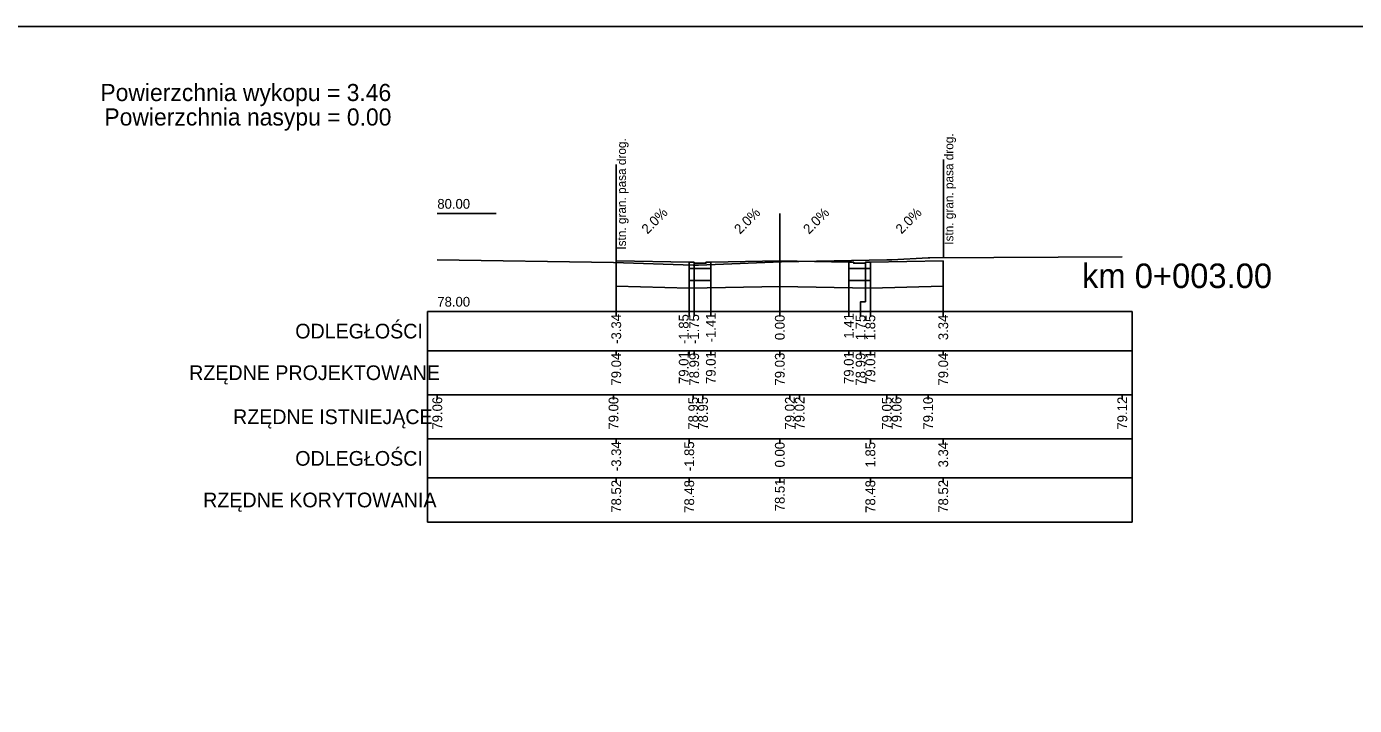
# Model space of a CAD drawing. Extents: x 7492871 to 7493499, y 5802964 to 5802992.
# Drawn here: x 7493105.36 to 7493132.5, y 5802978.41 to 5802992.28 of the extents above; entities that cross this region are included whole.
import ezdxf

# ---------------------------------------------------------------- set-up
doc = ezdxf.new("R2010")
doc.units = 0
for name, color, linetype in [('_wydruk', 7, 'Continuous'), ('d_pop_nasyp_opis', 7, 'Continuous'), ('d_pop_wykop_opis', 7, 'Continuous'), ('opisy_ramki_pop', 7, 'Continuous'), ('pop_comp_kostka', 7, 'Continuous'), ('pop_comp_lawa', 7, 'Continuous'), ('pop_comp_scieralna', 7, 'Continuous'), ('pop_granica_istn', 7, 'Continuous'), ('pop_opis', 7, 'Continuous'), ('pop_os', 7, 'Continuous'), ('pop_pikietaz', 7, 'Continuous'), ('pop_teren', 7, 'Continuous')]:
    doc.layers.add(name, color=color, linetype=linetype)

msp = doc.modelspace()

# ---------------------------------------------------------------- linework, layer by layer
msp.add_lwpolyline([(7493117.413, 5802987.495), (7493118.905, 5802987.465), (7493119.005, 5802987.465), (7493119.006, 5802987.445), (7493119.245, 5802987.445), (7493119.246, 5802987.465), (7493119.346, 5802987.465), (7493120.756, 5802987.493), (7493122.166, 5802987.465), (7493122.266, 5802987.465), (7493122.267, 5802987.445), (7493122.506, 5802987.445), (7493122.507, 5802987.465), (7493122.607, 5802987.465), (7493124.097, 5802987.495)])
at = {"layer": '_wydruk'}
msp.add_lwpolyline([(7492871.369, 5802992.281), (7493499.283, 5802992.281), (7493499.283, 5802963.881), (7492871.369, 5802963.881)], close=True, dxfattribs=at)
at = {"layer": 'opisy_ramki_pop'}
for points in [[(7493117.413, 5802986.975), (7493117.413, 5802986.659), (7493117.413, 5802986.659), (7493117.413, 5802986.459)], [(7493118.905, 5802986.936), (7493118.905, 5802986.659), (7493118.905, 5802986.659), (7493118.905, 5802986.459)], [(7493120.756, 5802986.973), (7493120.756, 5802986.659), (7493120.756, 5802986.659), (7493120.756, 5802986.459)], [(7493122.607, 5802986.936), (7493122.607, 5802986.659), (7493122.607, 5802986.659), (7493122.607, 5802986.459)], [(7493124.097, 5802986.975), (7493124.097, 5802986.659), (7493124.097, 5802986.659), (7493124.097, 5802986.459)]]:
    msp.add_lwpolyline(points, dxfattribs=at)
at = {"layer": 'pop_comp_kostka'}
for p, q in [((7493119.005, 5802987.465), (7493118.905, 5802987.465)), ((7493118.905, 5802987.465), (7493118.905, 5802987.335)), ((7493119.006, 5802987.445), (7493119.005, 5802987.465)), ((7493119.245, 5802987.445), (7493119.006, 5802987.445)), ((7493119.246, 5802987.465), (7493119.245, 5802987.445)), ((7493119.346, 5802987.465), (7493119.246, 5802987.465)), ((7493119.346, 5802987.335), (7493119.346, 5802987.465)), ((7493122.266, 5802987.465), (7493122.166, 5802987.465)), ((7493122.166, 5802987.465), (7493122.166, 5802987.335)), ((7493122.267, 5802987.445), (7493122.266, 5802987.465)), ((7493122.506, 5802987.445), (7493122.267, 5802987.445)), ((7493122.507, 5802987.465), (7493122.506, 5802987.445)), ((7493122.607, 5802987.465), (7493122.507, 5802987.465)), ((7493122.607, 5802987.335), (7493122.607, 5802987.465)), ((7493118.905, 5802987.335), (7493119.346, 5802987.335)), ((7493122.166, 5802987.335), (7493122.607, 5802987.335))]:
    msp.add_line(p, q, dxfattribs=at)
at = {"layer": 'pop_comp_lawa'}
for p, q in [((7493119.346, 5802987.335), (7493118.905, 5802987.335)), ((7493118.905, 5802987.335), (7493118.905, 5802987.095)), ((7493119.346, 5802987.095), (7493119.346, 5802987.335)), ((7493122.607, 5802987.335), (7493122.166, 5802987.335)), ((7493122.166, 5802987.335), (7493122.166, 5802987.095)), ((7493122.607, 5802987.095), (7493122.607, 5802987.335)), ((7493118.905, 5802987.095), (7493119.346, 5802987.095)), ((7493122.166, 5802987.095), (7493122.607, 5802987.095))]:
    msp.add_line(p, q, dxfattribs=at)
at = {"layer": 'pop_comp_scieralna'}
for p, q in [((7493118.905, 5802987.465), (7493117.413, 5802987.495)), ((7493117.413, 5802987.495), (7493117.413, 5802986.975)), ((7493118.905, 5802987.095), (7493118.905, 5802987.465)), ((7493120.756, 5802987.493), (7493119.346, 5802987.465)), ((7493119.346, 5802987.465), (7493119.346, 5802987.095)), ((7493120.756, 5802986.973), (7493120.756, 5802987.493)), ((7493122.166, 5802987.465), (7493120.756, 5802987.493)), ((7493120.756, 5802987.493), (7493120.756, 5802986.973)), ((7493122.166, 5802987.095), (7493122.166, 5802987.465)), ((7493124.097, 5802987.495), (7493122.607, 5802987.465)), ((7493122.607, 5802987.465), (7493122.607, 5802987.095)), ((7493124.097, 5802986.975), (7493124.097, 5802987.495)), ((7493117.413, 5802986.975), (7493118.905, 5802986.936)), ((7493119.346, 5802987.095), (7493118.905, 5802987.095)), ((7493118.905, 5802986.936), (7493120.756, 5802986.973)), ((7493120.756, 5802986.973), (7493122.607, 5802986.936)), ((7493122.607, 5802987.095), (7493122.166, 5802987.095)), ((7493122.607, 5802986.936), (7493124.097, 5802986.975))]:
    msp.add_line(p, q, dxfattribs=at)
at = {"layer": 'pop_granica_istn'}
for p, q in [((7493117.413, 5802987.963), (7493117.413, 5802989.463)), ((7493124.105, 5802988.062), (7493124.105, 5802989.562)), ((7493124.105, 5802987.562), (7493124.105, 5802988.062)), ((7493117.413, 5802987.463), (7493117.413, 5802987.963))]:
    msp.add_line(p, q, dxfattribs=at)
at = {"layer": 'pop_opis'}
for p, q in [((7493113.756, 5802988.459), (7493114.956, 5802988.459)), ((7493113.556, 5802986.459), (7493113.556, 5802984.759)), ((7493113.556, 5802986.459), (7493113.556, 5802984.759)), ((7493113.556, 5802986.459), (7493113.556, 5802984.759)), ((7493113.556, 5802986.459), (7493113.556, 5802984.759)), ((7493113.756, 5802986.459), (7493114.956, 5802986.459)), ((7493117.413, 5802986.359), (7493117.413, 5802986.459)), ((7493118.905, 5802986.359), (7493118.905, 5802986.459)), ((7493119.006, 5802986.359), (7493119.006, 5802986.459)), ((7493119.346, 5802986.359), (7493119.346, 5802986.459)), ((7493120.756, 5802986.359), (7493120.756, 5802986.459)), ((7493122.166, 5802986.359), (7493122.166, 5802986.459)), ((7493122.407, 5802986.359), (7493122.407, 5802986.459)), ((7493122.607, 5802986.359), (7493122.607, 5802986.459)), ((7493124.097, 5802986.359), (7493124.097, 5802986.459)), ((7493113.556, 5802985.659), (7493127.956, 5802985.659)), ((7493113.556, 5802985.659), (7493127.956, 5802985.659)), ((7493113.556, 5802985.659), (7493127.956, 5802985.659)), ((7493113.556, 5802985.659), (7493127.956, 5802985.659)), ((7493117.413, 5802985.559), (7493117.413, 5802985.659)), ((7493118.905, 5802985.559), (7493118.905, 5802985.659)), ((7493119.006, 5802985.559), (7493119.006, 5802985.659)), ((7493119.346, 5802985.559), (7493119.346, 5802985.659)), ((7493120.756, 5802985.559), (7493120.756, 5802985.659)), ((7493122.166, 5802985.559), (7493122.166, 5802985.659)), ((7493122.407, 5802985.559), (7493122.407, 5802985.659)), ((7493122.607, 5802985.559), (7493122.607, 5802985.659)), ((7493124.097, 5802985.559), (7493124.097, 5802985.659)), ((7493113.556, 5802984.759), (7493113.556, 5802983.859)), ((7493113.756, 5802984.659), (7493113.756, 5802984.759)), ((7493117.357, 5802984.659), (7493117.357, 5802984.759)), ((7493118.986, 5802984.659), (7493118.986, 5802984.759)), ((7493119.186, 5802984.659), (7493119.186, 5802984.759)), ((7493120.961, 5802984.659), (7493120.961, 5802984.759)), ((7493121.161, 5802984.659), (7493121.161, 5802984.759)), ((7493122.944, 5802984.659), (7493122.944, 5802984.759)), ((7493123.144, 5802984.659), (7493123.144, 5802984.759)), ((7493123.787, 5802984.659), (7493123.787, 5802984.759)), ((7493127.756, 5802984.659), (7493127.756, 5802984.759)), ((7493113.556, 5802983.859), (7493113.556, 5802982.159)), ((7493117.413, 5802983.759), (7493117.413, 5802983.859)), ((7493118.905, 5802983.759), (7493118.905, 5802983.859)), ((7493120.756, 5802983.759), (7493120.756, 5802983.859)), ((7493122.607, 5802983.759), (7493122.607, 5802983.859)), ((7493124.097, 5802983.759), (7493124.097, 5802983.859)), ((7493113.556, 5802983.059), (7493127.956, 5802983.059)), ((7493117.413, 5802982.959), (7493117.413, 5802983.059)), ((7493118.905, 5802982.959), (7493118.905, 5802983.059)), ((7493120.756, 5802982.959), (7493120.756, 5802983.059)), ((7493122.607, 5802982.959), (7493122.607, 5802983.059)), ((7493124.097, 5802982.959), (7493124.097, 5802983.059))]:
    msp.add_line(p, q, dxfattribs=at)
for points in [[(7493117.413, 5802987.495), (7493117.413, 5802986.659), (7493117.413, 5802986.659), (7493117.413, 5802986.459)], [(7493118.905, 5802987.465), (7493118.905, 5802986.659), (7493118.905, 5802986.659), (7493118.905, 5802986.459)], [(7493119.006, 5802987.445), (7493119.006, 5802986.659), (7493119.006, 5802986.659), (7493119.006, 5802986.459)], [(7493119.346, 5802987.465), (7493119.346, 5802986.659), (7493119.346, 5802986.659), (7493119.346, 5802986.459)], [(7493120.756, 5802987.493), (7493120.756, 5802986.659), (7493120.756, 5802986.659), (7493120.756, 5802986.459)], [(7493122.166, 5802987.465), (7493122.166, 5802986.659), (7493122.166, 5802986.659), (7493122.166, 5802986.459)], [(7493122.506, 5802987.445), (7493122.506, 5802986.659), (7493122.407, 5802986.659), (7493122.407, 5802986.459)], [(7493122.607, 5802987.465), (7493122.607, 5802986.659), (7493122.607, 5802986.659), (7493122.607, 5802986.459)], [(7493124.097, 5802987.495), (7493124.097, 5802986.659), (7493124.097, 5802986.659), (7493124.097, 5802986.459)]]:
    msp.add_lwpolyline(points, dxfattribs=at)
for points in [[(7493113.556, 5802986.459), (7493113.556, 5802984.759), (7493127.956, 5802984.759), (7493127.956, 5802986.459)], [(7493113.556, 5802986.459), (7493113.556, 5802984.759), (7493127.956, 5802984.759), (7493127.956, 5802986.459)], [(7493113.556, 5802986.459), (7493113.556, 5802984.759), (7493127.956, 5802984.759), (7493127.956, 5802986.459)], [(7493113.556, 5802986.459), (7493113.556, 5802984.759), (7493127.956, 5802984.759), (7493127.956, 5802986.459)], [(7493113.556, 5802984.759), (7493113.556, 5802983.859), (7493127.956, 5802983.859), (7493127.956, 5802984.759)], [(7493113.556, 5802983.859), (7493113.556, 5802982.159), (7493127.956, 5802982.159), (7493127.956, 5802983.859)]]:
    msp.add_lwpolyline(points, close=True, dxfattribs=at)
at = {"layer": 'pop_os'}
msp.add_line((7493120.756, 5802988.459), (7493120.756, 5802986.459), dxfattribs=at)
at = {"layer": 'pop_teren'}
msp.add_lwpolyline([(7493113.756, 5802987.515), (7493117.357, 5802987.464), (7493118.986, 5802987.407), (7493119.093, 5802987.407), (7493120.961, 5802987.481), (7493121.148, 5802987.481), (7493122.944, 5802987.514), (7493123.045, 5802987.516), (7493123.787, 5802987.556), (7493123.823, 5802987.558), (7493127.756, 5802987.577)], dxfattribs=at)

# ---------------------------------------------------------------- texts
at = {"layer": 'd_pop_nasyp_opis'}
msp.add_text('Powierzchnia nasypu = 0.00', height=0.35, dxfattribs=at).set_placement((7493106.951, 5802990.259))
at = {"layer": 'd_pop_wykop_opis'}
msp.add_text('Powierzchnia wykopu = 3.46', height=0.35, dxfattribs=at).set_placement((7493106.869, 5802990.759))
at = {"layer": 'pop_granica_istn'}
for p in [(7493117.611, 5802987.724), (7493124.303, 5802987.824)]:
    msp.add_text('Istn. gran. pasa drog.', height=0.18, rotation=90, dxfattribs=at).set_placement(p)
at = {"layer": 'pop_opis'}
for s, height, p in [('80.00', 0.2, (7493113.756, 5802988.559)), ('78.00', 0.2, (7493113.756, 5802986.559)), ('ODLEGŁOŚCI', 0.3, (7493110.852, 5802985.909)), ('ODLEGŁOŚCI', 0.3, (7493110.852, 5802985.909)), ('ODLEGŁOŚCI', 0.3, (7493110.852, 5802985.909)), ('ODLEGŁOŚCI', 0.3, (7493110.852, 5802985.909)), ('RZĘDNE PROJEKTOWANE', 0.3, (7493108.684, 5802985.059)), ('RZĘDNE PROJEKTOWANE', 0.3, (7493108.684, 5802985.059)), ('RZĘDNE PROJEKTOWANE', 0.3, (7493108.684, 5802985.059)), ('RZĘDNE PROJEKTOWANE', 0.3, (7493108.684, 5802985.059)), ('RZĘDNE ISTNIEJĄCE', 0.3, (7493109.581, 5802984.159)), ('ODLEGŁOŚCI', 0.3, (7493110.852, 5802983.309)), ('RZĘDNE KORYTOWANIA', 0.3, (7493108.97, 5802982.459))]:
    msp.add_text(s, height=height, dxfattribs=at).set_placement(p)
for s, rotation, p in [('2.0%', 45, (7493118.05, 5802988.03)), ('2.0%', 45, (7493119.943, 5802988.029)), ('2.0%', 45, (7493121.353, 5802988.029)), ('2.0%', 45, (7493123.243, 5802988.03)), ('-3.34', 90, (7493117.513, 5802985.798)), ('-1.85', 90, (7493118.892, 5802985.796)), ('-1.75', 90, (7493119.106, 5802985.796)), ('-1.41', 90, (7493119.446, 5802985.829)), ('0.00', 90, (7493120.856, 5802985.874)), ('1.41', 90, (7493122.266, 5802985.905)), ('1.75', 90, (7493122.507, 5802985.873)), ('1.85', 90, (7493122.707, 5802985.873)), ('3.34', 90, (7493124.197, 5802985.874)), ('79.04', 90, (7493117.513, 5802984.947)), ('79.01', 90, (7493118.892, 5802984.978)), ('78.99', 90, (7493119.106, 5802984.946)), ('79.01', 90, (7493119.446, 5802984.978)), ('79.03', 90, (7493120.856, 5802984.947)), ('79.01', 90, (7493122.266, 5802984.978)), ('78.99', 90, (7493122.507, 5802984.946)), ('79.01', 90, (7493122.707, 5802984.978)), ('79.04', 90, (7493124.197, 5802984.947)), ('79.06', 90, (7493113.856, 5802984.047)), ('79.00', 90, (7493117.457, 5802984.047)), ('78.95', 90, (7493119.086, 5802984.045)), ('78.95', 90, (7493119.286, 5802984.045)), ('79.02', 90, (7493121.061, 5802984.048)), ('79.02', 90, (7493121.261, 5802984.048)), ('79.05', 90, (7493123.044, 5802984.045)), ('79.06', 90, (7493123.244, 5802984.047)), ('79.10', 90, (7493123.887, 5802984.047)), ('79.12', 90, (7493127.856, 5802984.048)), ('-3.34', 90, (7493117.513, 5802983.198)), ('-1.85', 90, (7493119.005, 5802983.196)), ('0.00', 90, (7493120.856, 5802983.274)), ('1.85', 90, (7493122.707, 5802983.273)), ('3.34', 90, (7493124.197, 5802983.274)), ('78.52', 90, (7493117.513, 5802982.348)), ('78.48', 90, (7493119.005, 5802982.346)), ('78.51', 90, (7493120.856, 5802982.378)), ('78.48', 90, (7493122.707, 5802982.346)), ('78.52', 90, (7493124.197, 5802982.348))]:
    msp.add_text(s, height=0.2, rotation=rotation, dxfattribs=at).set_placement(p)
at = {"layer": 'pop_pikietaz'}
msp.add_text('km 0+003.00', height=0.5, dxfattribs=at).set_placement((7493126.933, 5802986.939))

doc.saveas('drawing.dxf')
